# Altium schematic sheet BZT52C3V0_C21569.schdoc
size 127 x 101 mm
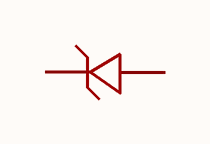
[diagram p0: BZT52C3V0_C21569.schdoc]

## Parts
ZD?  bzt52c3v0  [SOD-123_L2.8-W1.8-LS3.7-RD]  (value not drawn)

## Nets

Not connected (* = marked no-connect by the designer): ZD? 1(K) 2(A)

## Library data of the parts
ZD? = bzt52c3v0: 二极管配置:1个独立式;稳压值(标称值):3V;稳压值(范围):2.8V~3.2V;耗散功率(Pd):500mW;; Manufacturer: CJ(江苏长电/长晶); Symbol: BZT52C3V0_C21569; AddInBom: yes; ModelId: 7884390a25fb4c08947731ebfba7e3f8; ModelTransform: 144.8816,62.992,0,0,0,0,0,0,0; Diode Configuration: 1个独立式; Zener Voltage(Nom): 3V; Reverse Leakage Current (Ir): 10uA; Pd - Power Dissipation: 500mW; Impedance(Zzt): 95Ω; Impedance(Zzk): 600Ω; Operating Junction Temperature Range: -55℃~+150℃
